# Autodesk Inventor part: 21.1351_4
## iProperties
Created: 2006-12
Part Number: 21.1351_4
Document SubType Name: Modeling
Designer: Andy Moles
Material: Stainless Steel
Density: 8.08 g/cm^3
Mass: 4.37332 g
Surface Area: 8.34272 cm^2
Volume: 0.541252 cm^3
Author: Andy Moles
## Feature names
1. Extrusion1
2. Revolution1
3. Fillet2
4. Extrusion3
